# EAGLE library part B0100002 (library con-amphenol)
AMPHENOL CONNECTOR
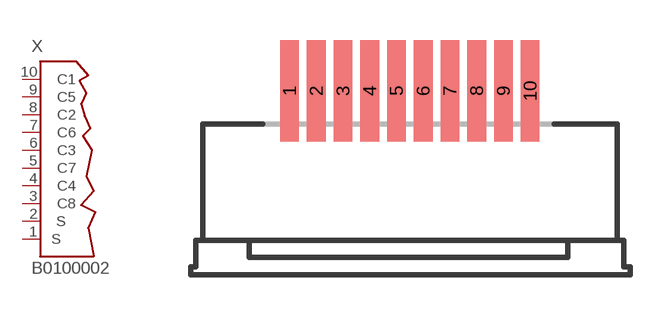
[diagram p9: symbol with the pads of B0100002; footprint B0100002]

Designator prefix X

## B0100002 (OC_FARNELL: unknown; OC_NEWARK: unknown)  [B0100002]
1  S1  pas
2  S2  pas
3  C8  pas
4  C4  pas
5  C7  pas
6  C3  pas
7  C6  pas
8  C2  pas
9  C5  pas
10  C1  pas

## Footprint B0100002 (pad centres in mm)
AMPHENOL CONNECTOR
smd 0.7 x 3.8: 1 -4.5,2.91; 2 -3.5,2.91; 3 -2.5,2.91; 4 -1.5,2.91; 5 -0.5,2.91; 6 0.5,2.91; 7 1.5,2.91; 8 2.5,2.91; 9 3.5,2.91; 10 4.5,2.91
